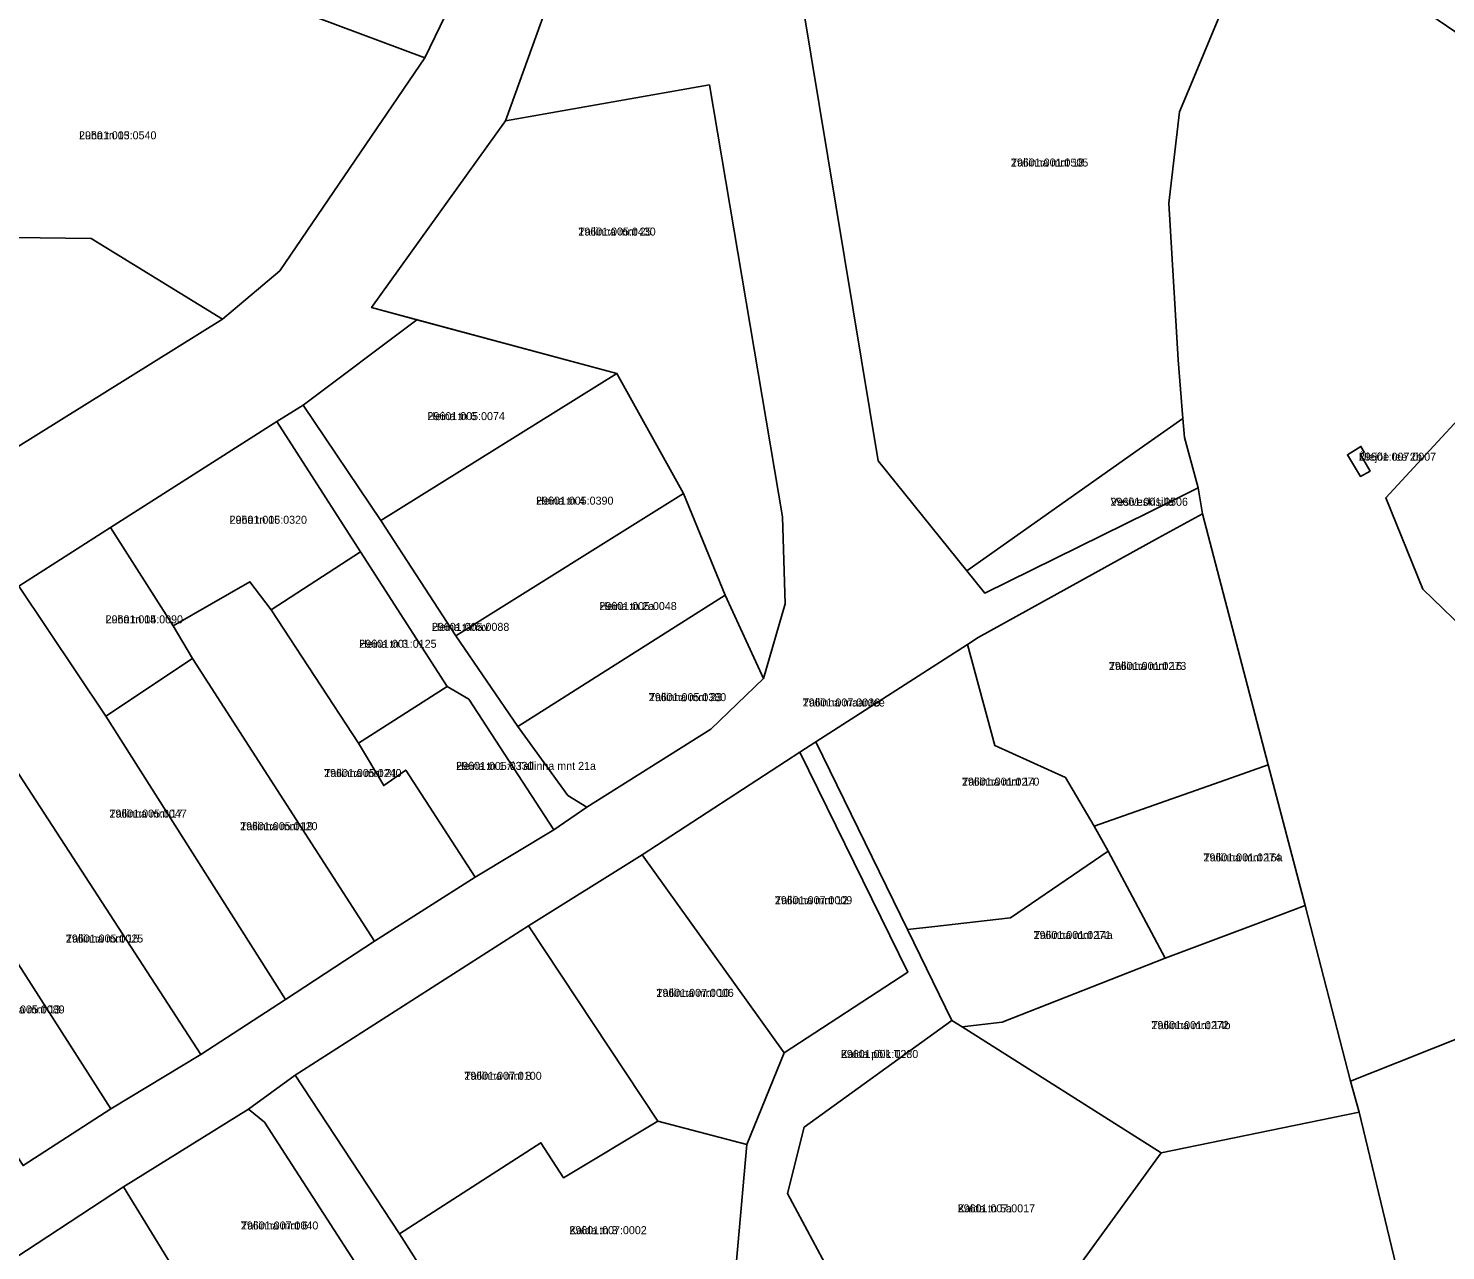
# Model space of a CAD drawing. Extents: x 518839 to 525192, y 6573164 to 6576561.
# Drawn here: x 524522.2 to 524787.8, y 6574621.6 to 6574850.6 of the extents above; entities that cross this region are included whole.
import ezdxf

# ---------------------------------------------------------------- set-up
doc = ezdxf.new("R2010")
doc.units = 0
for name, color, linetype in [('L_AADRESS', 7, 'Continuous'), ('PIIR', 7, 'Continuous'), ('TUNNUS', 7, 'Continuous')]:
    doc.layers.add(name, color=color, linetype=linetype)

msp = doc.modelspace()

# ---------------------------------------------------------------- linework, layer by layer
at = {"layer": 'PIIR'}
for points in [[(524641.1, 6574914.98), (524611.6, 6574833.26), (524586.54, 6574798.3), (524594.99, 6574796.03), (524573.68, 6574780.04), (524568.8, 6574776.94), (524537.6, 6574757.06), (524520.43, 6574746.1)], [(524521.22, 6574637.52), (524537.64, 6574648.16), (524554.52, 6574658.36), (524570.42, 6574668.67), (524587.06, 6574679.56), (524605.94, 6574691.54), (524620.68, 6574700.42), (524626.89, 6574704.66), (524650.11, 6574719.31), (524659.96, 6574728.78), (524664.02, 6574742.77), (524663.53, 6574759.1), (524649.86, 6574840.03), (524611.6, 6574833.26), (524641.1, 6574914.98)], [(524659.41, 6574902.78), (524681.5, 6574769.6), (524698.1, 6574748.94), (524701.46, 6574744.79), (524732.28, 6574759.99), (524741.47, 6574764.52), (524742.28, 6574759.67), (524734.05, 6574755.13), (524700.22, 6574736.47), (524698.2, 6574735.17), (524669.8, 6574716.91), (524666.82, 6574714.96), (524637.22, 6574695.76), (524615.96, 6574682.44), (524572.2, 6574654.48), (524563.49, 6574648.12), (524540.05, 6574633.54), (524515.81, 6574617.7)], [(524476.15, 6574744.79), (524558.58, 6574796.1), (524569.32, 6574805.16), (524596.49, 6574845.07), (524600.32, 6574852.95)], [(524821.3, 6574709.05), (524783.54, 6574745.56), (524776.61, 6574762.63), (524799.92, 6574787.89)], [(524800.69, 6574521.12), (524779.97, 6574520.21), (524779.42, 6574557.51), (524778.52, 6574619.01), (524771.64, 6574647.53), (524769.98, 6574653.34), (524778.82, 6574656.87), (524833.42, 6574678.59)]]:
    msp.add_lwpolyline(points, dxfattribs=at)
for points in [[(524659.41, 6574902.78), (524663, 6574914.88), (524737.85, 6574880.01), (524753.32, 6574872.81), (524747.88, 6574858.83), (524739.57, 6574838.88), (524737.94, 6574834.97), (524735.95, 6574817.86), (524737.68, 6574788.53), (524738.57, 6574777.54), (524729.8, 6574771.34), (524698.1, 6574748.94), (524681.5, 6574769.6)], [(524349.87, 6574732.89), (524359.23, 6574744.29), (524396.75, 6574777.58), (524429.03, 6574804.68), (524472.25, 6574842.16), (524516.52, 6574885.17), (524538.41, 6574874.85), (524560.53, 6574864.54), (524577.14, 6574856.56), (524584.79, 6574857.73), (524596.22, 6574854.46), (524600.32, 6574852.95), (524596.49, 6574845.07), (524547.26, 6574863.55), (524507.92, 6574863.47), (524483.08, 6574834.9), (524457.28, 6574812.27), (524431.07, 6574789.59), (524377.56, 6574742.71), (524324.1, 6574693.4), (524315.12, 6574699.28)], [(524737.68, 6574788.53), (524735.95, 6574817.86), (524737.94, 6574834.97), (524739.57, 6574838.88), (524747.88, 6574858.83), (524753.32, 6574872.81), (524762.62, 6574868.39), (524795.98, 6574845.68), (524841.36, 6574823.41), (524839.82, 6574820.55), (524843.29, 6574818.74), (524799.92, 6574787.89), (524776.61, 6574762.63), (524783.54, 6574745.56), (524821.3, 6574709.05), (524833.42, 6574678.59), (524778.82, 6574656.87), (524769.98, 6574653.34), (524761.5, 6574686.24), (524754.6, 6574712.61), (524742.28, 6574759.67), (524741.47, 6574764.52), (524738.87, 6574773.94), (524738.57, 6574777.54)], [(524483.08, 6574834.9), (524507.92, 6574863.47), (524547.26, 6574863.55), (524596.49, 6574845.07), (524569.32, 6574805.16), (524558.58, 6574796.1), (524534, 6574811.24), (524457.28, 6574812.27)], [(524649.86, 6574840.03), (524663.53, 6574759.1), (524664.02, 6574742.77), (524659.96, 6574728.78), (524652.79, 6574744.44), (524645, 6574763.44), (524632.49, 6574785.97), (524586.54, 6574798.3), (524611.6, 6574833.26)], [(524461.68, 6574769.71), (524435.5, 6574770.07), (524431.07, 6574789.59), (524457.28, 6574812.27), (524534, 6574811.24), (524558.58, 6574796.1), (524476.15, 6574744.79)], [(524573.68, 6574780.04), (524594.99, 6574796.03), (524632.49, 6574785.97), (524588.26, 6574758.39)], [(524645, 6574763.44), (524602.35, 6574736.77), (524588.26, 6574758.39), (524632.49, 6574785.97)], [(524568.8, 6574776.94), (524573.68, 6574780.04), (524588.26, 6574758.39), (524602.35, 6574736.77), (524613.91, 6574719.79), (524623.34, 6574706.89), (524626.89, 6574704.66), (524620.68, 6574700.42), (524604.77, 6574724.9), (524600.72, 6574727.28), (524584.48, 6574752.52)], [(524568.8, 6574776.94), (524584.48, 6574752.52), (524567.71, 6574741.63), (524563.74, 6574746.92), (524549.35, 6574738.65), (524537.6, 6574757.06)], [(524701.46, 6574744.79), (524698.1, 6574748.94), (524729.8, 6574771.34), (524738.57, 6574777.54), (524738.87, 6574773.94), (524741.47, 6574764.52), (524732.28, 6574759.99)], [(524772.59, 6574771.23), (524771.87, 6574770.77), (524773.68, 6574767.66), (524771.88, 6574766.65), (524769.44, 6574770.7), (524771.95, 6574772.28)], [(524769.44, 6574770.7), (524771.88, 6574766.65), (524773.68, 6574767.66), (524771.87, 6574770.77), (524772.59, 6574771.23), (524771.95, 6574772.28)], [(524645, 6574763.44), (524652.79, 6574744.44), (524613.91, 6574719.79), (524602.35, 6574736.77)], [(524703.36, 6574716.21), (524698.2, 6574735.17), (524700.22, 6574736.47), (524734.05, 6574755.13), (524742.28, 6574759.67), (524754.6, 6574712.61), (524746.63, 6574709.81), (524721.96, 6574701.13), (524716.6, 6574710.24)], [(524537.6, 6574757.06), (524549.35, 6574738.65), (524552.94, 6574732.54), (524536.72, 6574721.74), (524520.43, 6574746.1)], [(524584.08, 6574716.66), (524567.71, 6574741.63), (524584.48, 6574752.52), (524600.72, 6574727.28)], [(524563.74, 6574746.92), (524567.71, 6574741.63), (524584.08, 6574716.66), (524588.82, 6574708.72), (524592.92, 6574711.63), (524605.94, 6574691.54), (524587.06, 6574679.56), (524552.94, 6574732.54), (524549.35, 6574738.65)], [(524504.36, 6574735.95), (524520.43, 6574746.1), (524536.72, 6574721.74), (524570.42, 6574668.67), (524554.52, 6574658.36), (524520.57, 6574710.7)], [(524659.96, 6574728.78), (524650.11, 6574719.31), (524626.89, 6574704.66), (524623.34, 6574706.89), (524613.91, 6574719.79), (524652.79, 6574744.44)], [(524686.99, 6574681.78), (524669.8, 6574716.91), (524698.2, 6574735.17), (524703.36, 6574716.21), (524716.6, 6574710.24), (524721.96, 6574701.13), (524724.56, 6574696.41), (524706.3, 6574683.94), (524703.55, 6574683.63), (524692.09, 6574682.35)], [(524552.94, 6574732.54), (524587.06, 6574679.56), (524570.42, 6574668.67), (524536.72, 6574721.74)], [(524604.77, 6574724.9), (524620.68, 6574700.42), (524605.94, 6574691.54), (524592.92, 6574711.63), (524588.82, 6574708.72), (524584.08, 6574716.66), (524600.72, 6574727.28)], [(524687.02, 6574673.75), (524663.85, 6574658.67), (524637.22, 6574695.76), (524666.82, 6574714.96)], [(524666.82, 6574714.96), (524669.8, 6574716.91), (524686.99, 6574681.78), (524695.3, 6574664.74), (524667.63, 6574644.75), (524664.47, 6574632.29), (524679.45, 6574604.28), (524668.54, 6574598.45), (524653.5, 6574603.51), (524656.89, 6574641.46), (524663.85, 6574658.67), (524687.02, 6574673.75)], [(524724.56, 6574696.41), (524721.96, 6574701.13), (524746.63, 6574709.81), (524754.6, 6574712.61), (524761.5, 6574686.24), (524752.25, 6574682.78), (524735.25, 6574676.42)], [(524554.52, 6574658.36), (524537.64, 6574648.16), (524508.14, 6574694.17), (524503.93, 6574700.73), (524520.57, 6574710.7)], [(524695.3, 6574664.74), (524686.99, 6574681.78), (524692.09, 6574682.35), (524703.55, 6574683.63), (524706.3, 6574683.94), (524724.56, 6574696.41), (524735.25, 6574676.42), (524704.73, 6574664.42), (524697.2, 6574663.54)], [(524491.36, 6574683.23), (524508.14, 6574694.17), (524537.64, 6574648.16), (524521.22, 6574637.52)], [(524637.22, 6574695.76), (524663.85, 6574658.67), (524656.89, 6574641.46), (524640.19, 6574645.83), (524615.96, 6574682.44)], [(524734.5, 6574639.94), (524697.2, 6574663.54), (524704.73, 6574664.42), (524735.25, 6574676.42), (524752.25, 6574682.78), (524761.5, 6574686.24), (524769.98, 6574653.34), (524771.64, 6574647.53), (524761.87, 6574645.54)], [(524615.96, 6574682.44), (524640.19, 6574645.83), (524622.48, 6574635.23), (524618.28, 6574641.8), (524591.75, 6574624.76), (524572.2, 6574654.48)], [(524667.63, 6574644.75), (524695.3, 6574664.74), (524697.2, 6574663.54), (524734.5, 6574639.94), (524714.3, 6574612.07), (524685.59, 6574592.78), (524679.45, 6574604.28), (524664.47, 6574632.29)], [(524563.49, 6574648.12), (524572.2, 6574654.48), (524591.75, 6574624.76), (524599.66, 6574612.34), (524626.3, 6574570.33), (524636.7, 6574562.97), (524636.94, 6574559.24), (524643.5, 6574502.29), (524644.95, 6574489.1), (524651.82, 6574429.21), (524639.54, 6574428.13), (524638.25, 6574442.35), (524632.55, 6574498.54), (524627.73, 6574535.32), (524620.94, 6574556.2), (524613.94, 6574570.17), (524595.35, 6574600.76), (524588.87, 6574611.12), (524584.04, 6574618.52), (524566.43, 6574645.69)], [(524540.05, 6574633.54), (524563.49, 6574648.12), (524566.43, 6574645.69), (524584.04, 6574618.52), (524559.31, 6574602.05)], [(524622.48, 6574635.23), (524640.19, 6574645.83), (524656.89, 6574641.46), (524653.5, 6574603.51), (524604.13, 6574615.15), (524599.66, 6574612.34), (524591.75, 6574624.76), (524618.28, 6574641.8)], [(524685.59, 6574592.78), (524714.3, 6574612.07), (524734.5, 6574639.94), (524761.87, 6574645.54), (524771.64, 6574647.53), (524778.52, 6574619.01), (524779.42, 6574557.51), (524764.21, 6574557.29), (524759.21, 6574557.22), (524745.18, 6574585.67), (524729.98, 6574610.24), (524728.22, 6574613.15), (524686.03, 6574589.99)], [(524515.81, 6574617.7), (524540.05, 6574633.54), (524559.31, 6574602.05), (524535.06, 6574586.49)]]:
    msp.add_lwpolyline(points, close=True, dxfattribs=at)

# ---------------------------------------------------------------- texts
at = {"layer": 'L_AADRESS'}
for s, p in [('Luha tn 13', (524531.7, 6574829.83)), ('Tallinna mnt 18', (524706.36, 6574824.73)), ('Tallinna mnt 25', (524625.28, 6574811.79)), ('Heina tn 6', (524597.01, 6574777.21)), ('Ülejõe tee 2b', (524771.56, 6574769.61)), ('Heina tn 4', (524617.36, 6574761.37)), ('Vesiveskisilla', (524725.03, 6574761.16)), ('Luha tn 16', (524559.92, 6574757.79)), ('Heina tn 2a', (524629.22, 6574741.62)), ('Luha tn 14', (524536.68, 6574739.13)), ('Heina tänav', (524597.84, 6574737.72)), ('Heina tn 3', (524584.21, 6574734.55)), ('Tallinna mnt 16', (524724.72, 6574730.4)), ('Tallinna mnt 23', (524638.49, 6574724.55)), ('Tallinna maantee', (524667.33, 6574723.55)), ('Heina tn 1 // Tallinna mnt 21a', (524602.38, 6574711.67)), ('Tallinna mnt 21', (524577.64, 6574710.33)), ('Tallinna mnt 14', (524697.18, 6574708.72)), ('Tallinna mnt 17', (524537.39, 6574702.73)), ('Tallinna mnt 19', (524561.89, 6574700.37)), ('Tallinna mnt 16a', (524742.45, 6574694.52)), ('Tallinna mnt 12', (524662.12, 6574686.5)), ('Tallinna mnt 15', (524529.23, 6574679.32)), ('Tallinna mnt 14a', (524710.61, 6574679.98)), ('Tallinna mnt 10', (524639.91, 6574669.14)), ('Tallinna mnt 13', (524514.5, 6574666.03)), ('Tallinna mnt 14b', (524732.69, 6574663.09)), ('Kalda põik T2', (524674.49, 6574657.68)), ('Tallinna mnt 8', (524603.91, 6574653.6)), ('Kalda tn 5a', (524696.38, 6574628.76)), ('Tallinna mnt 6', (524562.04, 6574625.55)), ('Kalda tn 3', (524623.6, 6574624.67))]:
    msp.add_text(s, height=1.5, dxfattribs=at).set_placement(p)
at = {"layer": 'TUNNUS'}
for s, p in [('29601:005:0540', (524531.7, 6574829.83)), ('29601:001:0505', (524706.36, 6574824.73)), ('29601:005:0430', (524625.28, 6574811.79)), ('29601:005:0074', (524597.01, 6574777.21)), ('29601:007:0007', (524771.56, 6574769.61)), ('29601:005:0390', (524617.36, 6574761.37)), ('29601:001:0506', (524725.03, 6574761.16)), ('29601:005:0320', (524559.92, 6574757.79)), ('29601:005:0048', (524629.22, 6574741.62)), ('29601:005:0090', (524536.68, 6574739.13)), ('29601:005:0088', (524597.84, 6574737.72)), ('29601:001:0125', (524584.21, 6574734.55)), ('29601:001:0273', (524724.72, 6574730.4)), ('29601:005:0380', (524638.49, 6574724.55)), ('29601:007:0036', (524667.33, 6574723.55)), ('29601:005:0330', (524602.38, 6574711.67)), ('29601:005:0240', (524577.64, 6574710.33)), ('29601:001:0270', (524697.18, 6574708.72)), ('29601:005:0047', (524537.39, 6574702.73)), ('29601:005:0120', (524561.89, 6574700.37)), ('29601:001:0274', (524742.45, 6574694.52)), ('29601:007:0009', (524662.12, 6574686.5)), ('29601:005:0025', (524529.23, 6574679.32)), ('29601:001:0271', (524710.61, 6574679.98)), ('29601:007:0006', (524639.91, 6574669.14)), ('29601:005:0089', (524514.5, 6574666.03)), ('29601:001:0272', (524732.69, 6574663.09)), ('29601:001:0280', (524674.49, 6574657.68)), ('29601:007:0100', (524603.91, 6574653.6)), ('29601:007:0017', (524696.38, 6574628.76)), ('29601:007:0040', (524562.04, 6574625.55)), ('29601:007:0002', (524623.6, 6574624.67))]:
    msp.add_text(s, height=1.5, dxfattribs=at).set_placement(p)

doc.saveas('drawing.dxf')
